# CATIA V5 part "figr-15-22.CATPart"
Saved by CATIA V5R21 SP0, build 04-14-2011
Part number: Part1
Bounding box of the stored display mesh (mm): x -75 to 76, y -66.397 to 33.603, z 0 to 100
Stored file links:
  D:\CATIA V5R21 E-RESOURCES\CATIA-V5R21\catia-v5r21-prt\c15-catia-v5r20-prt\c15-catia-v5r21-figr-15-22.CATPart
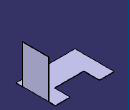
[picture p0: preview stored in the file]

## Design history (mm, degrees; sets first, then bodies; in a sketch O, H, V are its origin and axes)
SheetMetalParameters1: Thickness 1, BendRadius 1, KFactor 0.325257 {= log(min(100,max(20*SheetMetalParameters1.BendRadius,SheetMetalParameters1.Thickness)/SheetMetalParameters1.Thickness))/log(100)/2}, ReliefRadialLength 1, ReliefAxialLength 2, MinimumBendRadius 0
Body1 (main body)
  Sketch1 on xy-plane, origin (0, 0, 0), H (1, 0, 0), V (0, 1, 0)
    line L1 (-37.5, 33.6029) -> (-37.5, -6.3971)
    line L2 (-37.5, -6.3971) -> (37.5, -6.3971)
    line L3 (37.5, -6.3971) -> (37.5, 33.6029)
    line L4 (37.5, 33.6029) -> (75, 33.6029)
    line L5 (75, 33.6029) -> (75, -66.3971)
    line L6 (75, -66.3971) -> (-75, -66.3971)
    line L7 (-75, -66.3971) -> (-75, 33.6029)
    point P8 (-75, 33.6029)
    line L8 (-75, 33.6029) -> (-37.5, 33.6029)
    length L7 = 100
    length L1 = 40
    length L6 = 150
    distance L1 L3 = 75
    vertical: L1 V, L3 V, L5 V, L7 V
    horizontal: L2 H, L4 H, L6 H, L8 H
    coincidence: P8 L4
    symmetry: L7 L5 V, L1 L3 V
  Wall1: Thickness 1, Profile Sketch1
  d_NewWallOnEdge1: NewWallOnEdge_Edge edge [face of Wall1 | face of Wall1], NewWallOnEdge_Length 100, NewWallOnEdge_HeightLimitOffset 0, NewWallOnEdge_WidthOffset1 -16, NewWallOnEdge_WidthOffset2 -17, NewWallOnEdge_Angle 90, NewWallOnEdge_BendRadiusValue 1 {= SheetMetalParameters1.BendRadius}, NewWallOnEdge_BendTable SheetMetalParameters1, KFacteur 0.325257 {= log(min(100,max(20*d_NewWallOnEdge1.Radius,SheetMetalParameters1.Thickness)/SheetMetalParameters1.Thickness))/log(100)/2}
